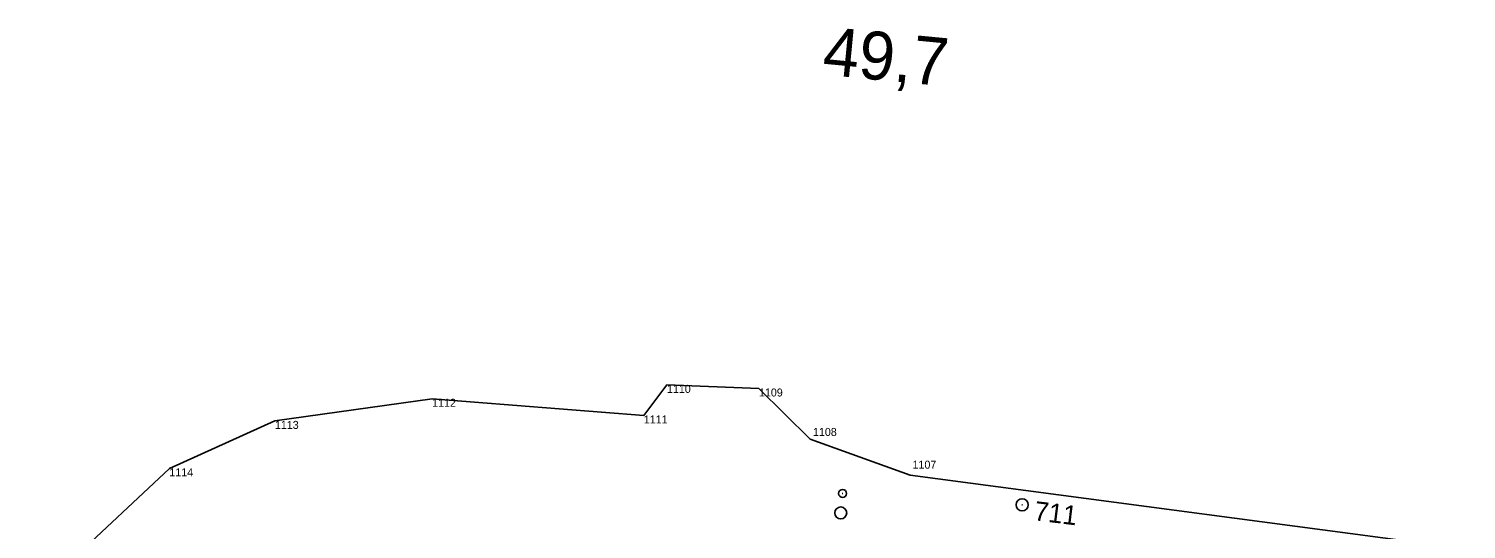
# Model space of a CAD drawing. Extents: x -678683 to -677755, y -1006946 to -1005971.
# Drawn here: x -678132.6 to -677953, y -1006341.2 to -1006278.6 of the extents above; entities that cross this region are included whole.
import ezdxf

# ---------------------------------------------------------------- set-up
doc = ezdxf.new("R2010")
doc.units = 0
for name, color, linetype in [('Stávající ŽBP', 7, 'Continuous'), ('SŽDC', 7, 'Continuous'), ('SŽDC - body', 7, 'Continuous'), ('Vrstva 7', 7, 'Continuous')]:
    doc.layers.add(name, color=color, linetype=linetype)

msp = doc.modelspace()

# ---------------------------------------------------------------- linework, layer by layer
at = {"layer": 'Stávající ŽBP'}
msp.add_line((-678008.55, -1006338.11), (-678008.45, -1006338.12), dxfattribs=at)
msp.add_circle((-678008.5, -1006338.11), 0.756, dxfattribs=at)
at = {"layer": 'SŽDC'}
for p, q in [((-678052.89, -1006323.12), (-678055.78, -1006326.94)), ((-678041.39, -1006323.57), (-678052.89, -1006323.12)), ((-678034.98, -1006329.89), (-678041.39, -1006323.57)), ((-678082.23, -1006324.86), (-678101.88, -1006327.62)), ((-678055.78, -1006326.94), (-678082.23, -1006324.86)), ((-678101.88, -1006327.62), (-678115.07, -1006333.55)), ((-678022.51, -1006334.41), (-678034.98, -1006329.89)), ((-678115.07, -1006333.55), (-678132.64, -1006350.02)), ((-677918.4, -1006348.18), (-678022.51, -1006334.41))]:
    msp.add_line(p, q, dxfattribs=at)
at = {"layer": 'SŽDC - body'}
for p, q in [((-678052.89, -1006323.12), (-678052.89, -1006323.12)), ((-678041.39, -1006323.57), (-678041.39, -1006323.57)), ((-678082.23, -1006324.86), (-678082.23, -1006324.86)), ((-678101.88, -1006327.62), (-678101.88, -1006327.62)), ((-678055.78, -1006326.94), (-678055.78, -1006326.94)), ((-678034.98, -1006329.89), (-678034.98, -1006329.89)), ((-678115.07, -1006333.55), (-678115.07, -1006333.55)), ((-678022.51, -1006334.41), (-678022.51, -1006334.41))]:
    msp.add_line(p, q, dxfattribs=at)
at = {"layer": 'Vrstva 7'}
msp.add_line((-678030.99, -1006336.68), (-678030.89, -1006336.69), dxfattribs=at)
for centre, radius in [((-678030.94, -1006336.69), 0.5), ((-678031.17, -1006339.12), 0.75)]:
    msp.add_circle(centre, radius, dxfattribs=at)

# ---------------------------------------------------------------- texts
at = {"layer": 'Stávající ŽBP'}
msp.add_text('711', height=2.4, rotation=352.972, dxfattribs=at).set_placement((-678007.1, -1006340.02))
at = {"layer": 'SŽDC - body'}
for s, p in [('1110', (-678052.89, -1006324.12)), ('1109', (-678041.39, -1006324.57)), ('1112', (-678082.23, -1006325.86)), ('1113', (-678101.88, -1006328.62)), ('1111', (-678055.78, -1006327.94)), ('1108', (-678034.64, -1006329.5)), ('1114', (-678115.07, -1006334.55)), ('1107', (-678022.2, -1006333.59))]:
    msp.add_text(s, height=1, dxfattribs=at).set_placement(p)
at = {"layer": 'Vrstva 7'}
msp.add_text('49,7', height=6, rotation=354.5133, dxfattribs=at).set_placement((-678033.57, -1006284.34))

doc.saveas('drawing.dxf')
